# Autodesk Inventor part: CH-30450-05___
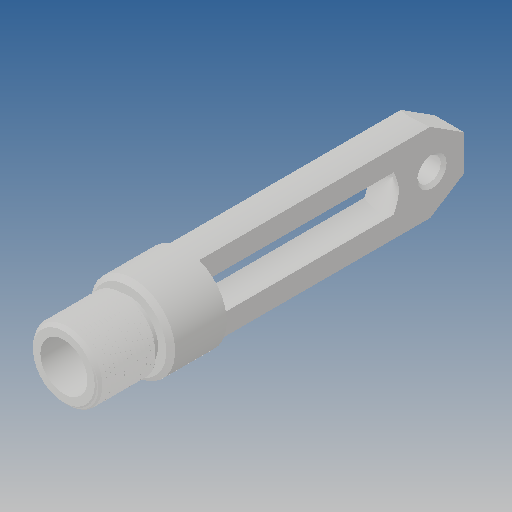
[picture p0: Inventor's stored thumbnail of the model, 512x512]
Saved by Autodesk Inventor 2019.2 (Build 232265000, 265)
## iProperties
Created: 2010-06
Part Number: CH-30450-05___
Material: Ogólny
Document SubType Name: Modeling
Designer: CADENGINEERING4
Density: 1 g/cm^3
Appearance: Domyślna
Author: CADENGINEERING4
Revision Number: ANY
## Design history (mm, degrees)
feature "NONE"
node "Bryła1"
